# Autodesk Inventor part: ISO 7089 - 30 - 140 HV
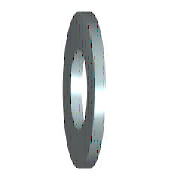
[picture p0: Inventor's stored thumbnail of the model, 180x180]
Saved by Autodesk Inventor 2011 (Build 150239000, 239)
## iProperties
IsCustomPart: 0
Created: 2009-02
Part Number: ISO 7089 - 30 - 140 HV
Material: Stainless Steel
Description: Plain washers - Normal series - Product grade A
Document SubType Name: Modeling
Standard: ISO 7089
Designer: V.de Jong
Standard Revision: Second edition 2000-06-01
Standards Organization: ISO
Language: en-US
Size Designation: 30 - 140 HV
Categories: <MemberInstance><Categories><Category DisplayName="Fasteners" InternalName="e4da775c-781d-43d5-af7c-5136215cf5a6" Mnemonic="FSTN"><Category DisplayName="Washers
Density: 8.08 g/cm^3
Mass: 55.2103 g
Surface Area: 45.0976 cm^2
Volume: 6.83296 cm^3
Author: V.de Jong
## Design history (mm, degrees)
body "Solid1"
sketch "Sketch"
  geometry: C1 r 28 at (0, 0); C2 r 15.5 at (0, 0); 1 further point
  constraints: 2 centre point, 2 coincident
  dimensions: "d0" = 31 diameter of C2 (= SD1); "d1" = 56 diameter of C1 (= SD2)
extrude "Body" new body sketch "Sketch" distance "d2" = 4 (= SD); taper "d3" = 0 deg
workaxis "Work Axis1"
workplane "Work Plane1"
other parameters: "SD1" = 31 [user parameter; used in 1 equation term], "SD2" = 56 [user parameter; used in 1 equation term], "SD" = 4 [user parameter; used in 1 equation term], "d4" = 0, "d5" = 0, "d6" = 0, "d7" = 0
